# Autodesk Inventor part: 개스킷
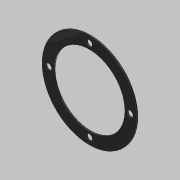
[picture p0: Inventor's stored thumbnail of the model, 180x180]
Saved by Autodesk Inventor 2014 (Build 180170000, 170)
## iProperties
Created: 2019-05
Part Number: 개스킷
Material: 고무
Document SubType Name: Modeling
Designer: mduedu
Density: 1 g/cm^3
Appearance: 고무 - 검은색 - 버전 1.1
Author: mduedu
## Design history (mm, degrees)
sketch "스케치1"
  geometry: C1 r 27 at (0, 0); C2 r 36 at (0, 0); 1 further point
  constraints: 2 centre point, 2 coincident
  dimensions: "d0" = 54 diameter of C1; "d1" = 72 diameter of C2
extrude "돌출1" new body sketch "스케치1" distance "d2" = 1; taper "d3" = 0 deg
sketch "스케치2" dims "d4" = 62
  geometry: C1 r 2.25 at (0, 31); 2 further points
  constraints: 2 vertical alignment, 1 centre point, 1 coincident, 2 other
  dimensions: "d5" = 4.5 diameter of C1
extrude "돌출2" cut sketch "스케치2" stored distance "d6" = 10; taper "d7" = 0 deg
node "솔리드1"
pattern_circular "원형 패턴1" dims angle "d9" = 360 deg
